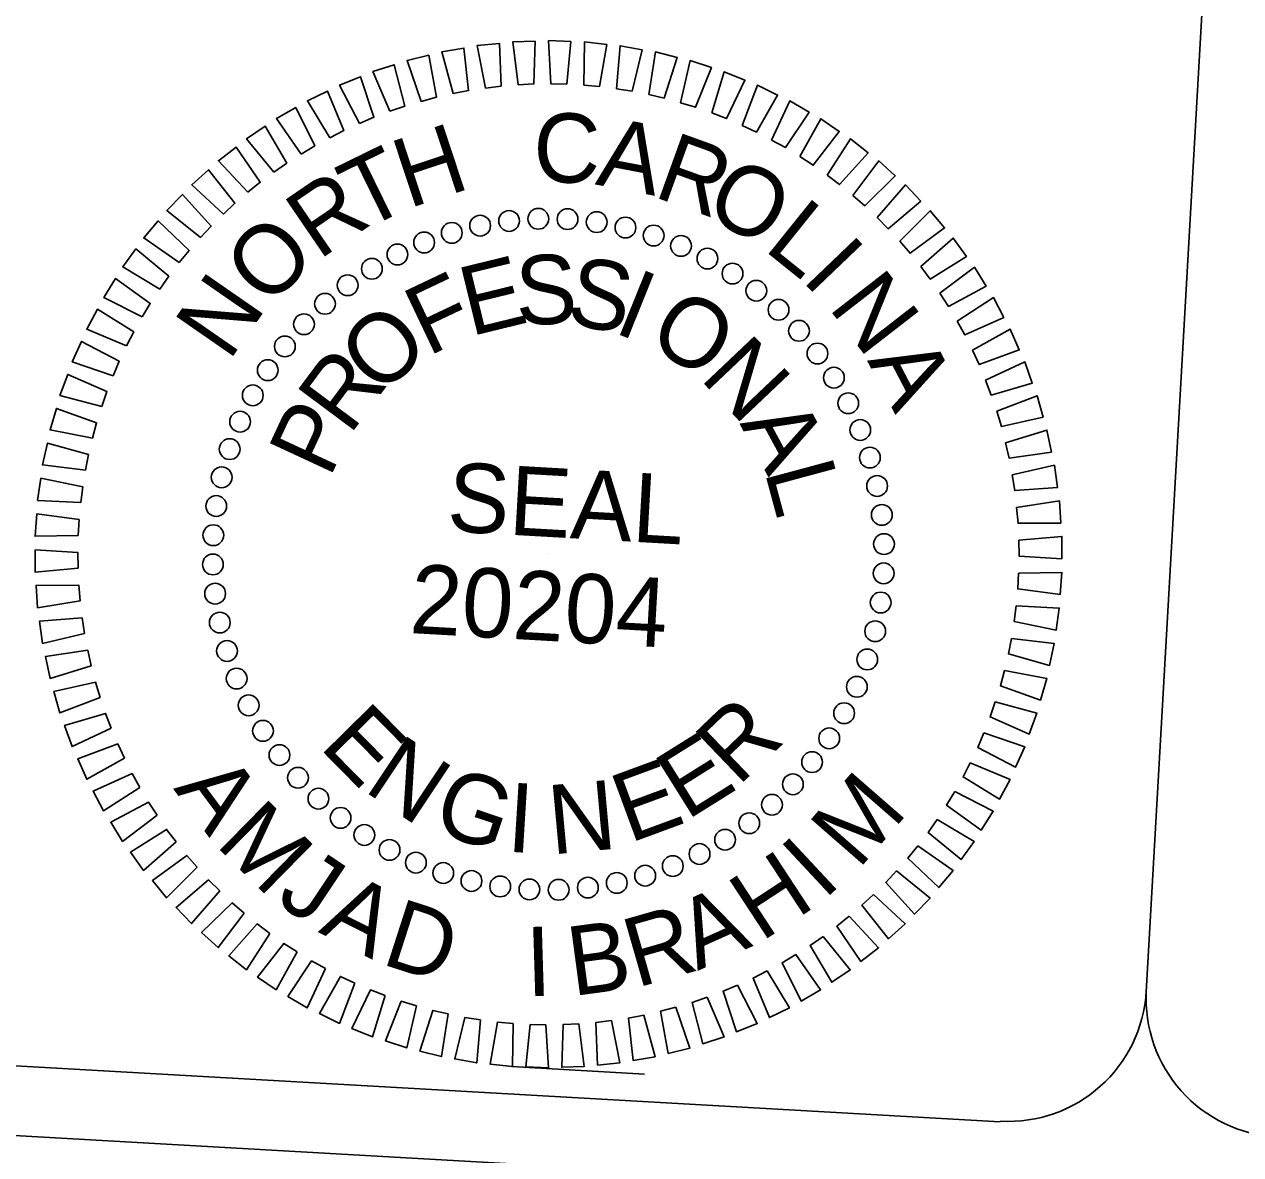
# Model space of a CAD drawing. Extents: x 2601627 to 2606907, y 616646 to 620530.
# Drawn here: x 2605867.9 to 2606131.5, y 617064.3 to 617309.3 of the extents above; entities that cross this region are included whole.
import ezdxf

# ---------------------------------------------------------------- set-up
doc = ezdxf.new("R2010")
doc.units = 0
doc.layers.add('Sheet PE Seal Cell', color=7, linetype='Continuous')
doc.layers.add('Sheet Title CELL', color=7, linetype='Continuous')

msp = doc.modelspace()

# ---------------------------------------------------------------- linework, layer by layer
at = {"layer": 'Sheet PE Seal Cell'}
msp.add_line((2605981.51, 617194.47), (2605981.51, 617194.47), dxfattribs=at)
for points in [[(2605967.85, 617295.52), (2605966.05, 617304.71), (2605970.87, 617305.19), (2605971.25, 617295.94)], [(2605974.93, 617296.23), (2605973.78, 617305.52), (2605978.62, 617305.66), (2605978.36, 617296.41)], [(2605982.05, 617296.44), (2605981.54, 617305.79), (2605986.39, 617305.59), (2605985.47, 617296.38)], [(2605989.16, 617296.15), (2605989.31, 617305.51), (2605994.13, 617304.98), (2605992.57, 617295.86)], [(2605996.23, 617295.37), (2605997.03, 617304.7), (2606001.81, 617303.83), (2605999.62, 617294.84)], [(2605953.92, 617292.63), (2605950.86, 617301.48), (2605955.57, 617302.63), (2605957.23, 617293.53)], [(2605960.83, 617294.32), (2605958.4, 617303.36), (2605963.18, 617304.18), (2605964.2, 617294.98)], [(2606003.24, 617294.1), (2606004.69, 617303.35), (2606009.39, 617302.15), (2606006.58, 617293.33)], [(2605947.14, 617290.47), (2605943.47, 617299.08), (2605948.09, 617300.56), (2605950.38, 617291.59)], [(2606010.13, 617292.34), (2606012.23, 617301.47), (2606016.83, 617299.94), (2606013.41, 617291.34)], [(2605940.53, 617287.84), (2605936.26, 617296.17), (2605940.77, 617297.97), (2605943.68, 617289.18)], [(2606016.89, 617290.11), (2606019.61, 617299.06), (2606024.1, 617297.22), (2606020.09, 617288.88)], [(2605934.11, 617284.75), (2605929.28, 617292.77), (2605933.65, 617294.87), (2605937.16, 617286.31)], [(2606023.48, 617287.4), (2606026.82, 617296.15), (2606031.17, 617294), (2606026.59, 617285.96)], [(2605927.93, 617281.22), (2605922.55, 617288.89), (2605926.76, 617291.29), (2605930.86, 617283)], [(2606029.86, 617284.25), (2606033.8, 617292.74), (2606037.99, 617290.3), (2606032.86, 617282.6)], [(2606036, 617280.66), (2606040.53, 617288.86), (2606044.53, 617286.12), (2606038.88, 617278.8)], [(2605922.01, 617277.28), (2605916.11, 617284.54), (2605920.14, 617287.23), (2605924.81, 617279.25)], [(2606041.88, 617276.65), (2606046.97, 617284.51), (2606050.78, 617281.51), (2606044.62, 617274.59)], [(2605916.38, 617272.92), (2605909.98, 617279.76), (2605913.82, 617282.73), (2605919.04, 617275.09)], [(2606047.47, 617272.24), (2606053.09, 617279.72), (2606056.68, 617276.46), (2606050.06, 617269.99)], [(2605911.06, 617268.19), (2605904.21, 617274.56), (2605907.83, 617277.79), (2605913.57, 617270.53)], [(2606052.73, 617267.45), (2606058.86, 617274.52), (2606062.21, 617271.02), (2606055.16, 617265.03)], [(2605906.09, 617263.09), (2605898.81, 617268.97), (2605902.19, 617272.45), (2605908.42, 617265.61)], [(2606057.65, 617262.3), (2606064.26, 617268.93), (2606067.36, 617265.2), (2606059.9, 617259.72)], [(2605901.49, 617257.67), (2605893.81, 617263.02), (2605896.95, 617266.72), (2605903.64, 617260.33)], [(2606062.2, 617256.83), (2606069.25, 617262.98), (2606072.08, 617259.04), (2606064.26, 617254.09)], [(2605897.27, 617251.93), (2605889.24, 617256.74), (2605892.11, 617260.65), (2605899.24, 617254.74)], [(2606066.35, 617251.05), (2606073.82, 617256.69), (2606076.37, 617252.57), (2606068.22, 617248.18)], [(2605893.47, 617245.91), (2605885.12, 617250.15), (2605887.71, 617254.25), (2605895.23, 617248.85)], [(2606070.09, 617244.99), (2606077.93, 617250.1), (2606080.19, 617245.81), (2606071.76, 617242)], [(2605890.1, 617239.65), (2605881.47, 617243.29), (2605883.77, 617247.56), (2605891.65, 617242.7)], [(2606073.4, 617238.69), (2606081.58, 617243.24), (2606083.53, 617238.8), (2606074.85, 617235.59)], [(2605887.17, 617233.16), (2605878.31, 617236.19), (2605880.31, 617240.61), (2605888.5, 617236.32)], [(2606076.26, 617232.17), (2606084.74, 617236.14), (2606086.37, 617231.58), (2606077.49, 617228.97)], [(2605884.7, 617226.48), (2605875.65, 617228.89), (2605877.33, 617233.44), (2605885.81, 617229.73)], [(2606078.66, 617225.47), (2606087.39, 617228.84), (2606088.71, 617224.17), (2606079.67, 617222.19)], [(2605882.7, 617219.65), (2605873.51, 617221.42), (2605874.87, 617226.08), (2605883.58, 617222.96)], [(2606080.59, 617218.62), (2606089.53, 617221.37), (2606090.52, 617216.62), (2606081.36, 617215.28)], [(2605881.19, 617212.7), (2605871.89, 617213.82), (2605872.92, 617218.56), (2605881.83, 617216.06)], [(2606082.03, 617211.65), (2606091.15, 617213.77), (2606091.8, 617208.96), (2606082.57, 617208.26)], [(2605880.16, 617205.66), (2605870.81, 617206.13), (2605871.51, 617210.93), (2605880.57, 617209.06)], [(2606082.98, 617204.6), (2606092.23, 617206.07), (2606092.54, 617201.24), (2606083.29, 617201.18)], [(2605879.62, 617198.56), (2605870.26, 617198.38), (2605870.63, 617203.21), (2605879.8, 617201.98)], [(2606083.44, 617197.49), (2606092.77, 617198.32), (2606092.74, 617193.47), (2606083.51, 617194.07)], [(2605879.59, 617191.44), (2605870.26, 617190.61), (2605870.29, 617195.46), (2605879.52, 617194.87)], [(2606083.4, 617190.38), (2606092.77, 617190.55), (2606092.4, 617185.72), (2606083.23, 617186.95)], [(2605880.05, 617184.34), (2605870.8, 617182.86), (2605870.49, 617187.7), (2605879.74, 617187.75)], [(2606082.87, 617183.28), (2606092.22, 617182.8), (2606091.52, 617178), (2606082.46, 617179.88)], [(2605881, 617177.28), (2605871.88, 617175.16), (2605871.23, 617179.97), (2605880.46, 617180.67)], [(2606081.84, 617176.23), (2606091.14, 617175.11), (2606090.11, 617170.37), (2606081.2, 617172.87)], [(2605882.44, 617170.31), (2605873.49, 617167.56), (2605872.51, 617172.31), (2605881.67, 617173.65)], [(2606080.33, 617169.28), (2606089.52, 617167.51), (2606088.16, 617162.85), (2606079.45, 617165.97)], [(2605884.37, 617163.46), (2605875.63, 617160.09), (2605874.32, 617164.76), (2605883.36, 617166.74)], [(2606078.33, 617162.45), (2606087.38, 617160.04), (2606085.7, 617155.49), (2606077.22, 617159.21)], [(2605886.77, 617156.76), (2605878.29, 617152.79), (2605876.65, 617157.36), (2605885.53, 617159.96)], [(2606075.86, 617155.77), (2606084.72, 617152.74), (2606082.72, 617148.32), (2606074.53, 617152.62)], [(2605889.63, 617150.24), (2605881.45, 617145.69), (2605879.5, 617150.13), (2605888.18, 617153.35)], [(2606072.93, 617149.29), (2606081.56, 617145.64), (2606079.26, 617141.37), (2606071.38, 617146.23)], [(2605892.94, 617143.94), (2605885.09, 617138.83), (2605882.84, 617143.12), (2605891.27, 617146.94)], [(2606069.56, 617143.02), (2606077.91, 617138.78), (2606075.32, 617134.68), (2606067.8, 617140.08)], [(2605896.68, 617137.89), (2605889.21, 617132.24), (2605886.66, 617136.37), (2605894.81, 617140.76)], [(2606065.75, 617137), (2606073.79, 617132.19), (2606070.92, 617128.29), (2606063.79, 617134.19)], [(2605900.83, 617132.11), (2605893.78, 617125.95), (2605890.95, 617129.89), (2605898.76, 617134.84)], [(2606061.54, 617131.27), (2606069.22, 617125.91), (2606066.08, 617122.21), (2606059.39, 617128.6)], [(2605905.38, 617126.63), (2605898.77, 617120), (2605895.67, 617123.73), (2605903.13, 617129.21)], [(2606056.94, 617125.84), (2606064.22, 617119.96), (2606060.84, 617116.49), (2606054.6, 617123.33)], [(2605910.3, 617121.49), (2605904.17, 617114.41), (2605900.81, 617117.91), (2605907.87, 617123.9)], [(2606051.97, 617120.74), (2606058.82, 617114.37), (2606055.2, 617111.14), (2606049.46, 617118.4)], [(2605915.56, 617116.69), (2605909.94, 617109.21), (2605906.35, 617112.47), (2605912.97, 617118.94)], [(2606046.65, 617116.01), (2606053.05, 617109.17), (2606049.21, 617106.21), (2606043.99, 617113.85)], [(2605921.15, 617112.28), (2605916.06, 617104.42), (2605912.25, 617107.43), (2605918.41, 617114.34)], [(2605927.03, 617108.27), (2605922.5, 617100.08), (2605918.49, 617102.81), (2605924.15, 617110.13)], [(2606041.02, 617111.66), (2606046.92, 617104.39), (2606042.89, 617101.7), (2606038.22, 617109.69)], [(2606035.1, 617107.71), (2606040.48, 617100.05), (2606036.27, 617097.64), (2606032.16, 617105.94)], [(2605933.17, 617104.68), (2605929.23, 617096.19), (2605925.04, 617098.64), (2605930.17, 617106.34)], [(2606028.92, 617104.18), (2606033.75, 617096.16), (2606029.38, 617094.06), (2606025.87, 617102.62)], [(2605939.55, 617101.53), (2605936.21, 617092.78), (2605931.86, 617094.93), (2605936.44, 617102.97)], [(2605946.14, 617098.83), (2605943.41, 617089.87), (2605938.93, 617091.71), (2605942.94, 617100.05)], [(2606022.5, 617101.09), (2606026.77, 617092.76), (2606022.26, 617090.97), (2606019.35, 617099.75)], [(2605952.9, 617096.59), (2605950.8, 617087.47), (2605946.2, 617088.99), (2605949.62, 617097.59)], [(2606009.11, 617096.3), (2606012.17, 617087.45), (2606007.46, 617086.3), (2606005.8, 617095.41)], [(2606015.89, 617098.46), (2606019.56, 617089.85), (2606014.94, 617088.38), (2606012.65, 617097.34)], [(2605959.79, 617094.83), (2605958.34, 617085.59), (2605953.64, 617086.78), (2605956.45, 617095.6)], [(2605966.8, 617093.56), (2605965.99, 617084.23), (2605961.22, 617085.1), (2605963.41, 617094.09)], [(2606002.19, 617094.61), (2606004.63, 617085.57), (2605999.85, 617084.76), (2605998.83, 617093.95)], [(2605973.87, 617092.78), (2605973.72, 617083.42), (2605968.9, 617083.95), (2605970.46, 617093.07)], [(2605980.98, 617092.5), (2605981.49, 617083.15), (2605976.64, 617083.34), (2605977.55, 617092.55)], [(2605988.1, 617092.71), (2605989.25, 617083.42), (2605984.41, 617083.27), (2605984.67, 617092.52)], [(2605995.18, 617093.41), (2605996.98, 617084.23), (2605992.15, 617083.74), (2605991.78, 617092.99)]]:
    msp.add_lwpolyline(points, close=True, dxfattribs=at)
for centre in [(2605966.71, 617265.69), (2605972.98, 617266.71), (2605979.31, 617267.18), (2605985.65, 617267.1), (2605991.97, 617266.46), (2605960.56, 617264.13), (2605998.2, 617265.28), (2606004.31, 617263.55), (2605954.57, 617262.04), (2606010.24, 617261.3), (2605948.78, 617259.44), (2606015.96, 617258.55), (2605943.24, 617256.34), (2606021.41, 617255.3), (2605938, 617252.77), (2606026.56, 617251.59), (2605933.08, 617248.75), (2606031.37, 617247.45), (2605928.53, 617244.32), (2606035.8, 617242.9), (2605924.39, 617239.52), (2606039.81, 617237.98), (2605920.68, 617234.37), (2606043.38, 617232.74), (2605917.44, 617228.91), (2606046.48, 617227.2), (2605914.68, 617223.2), (2606049.09, 617221.41), (2605912.43, 617217.26), (2606051.18, 617215.42), (2605910.7, 617211.15), (2606052.74, 617209.27), (2605909.52, 617204.92), (2606053.76, 617203), (2605908.88, 617198.6), (2606054.23, 617196.68), (2605908.8, 617192.26), (2606054.15, 617190.33), (2605909.27, 617185.93), (2606053.51, 617184.01), (2605910.29, 617179.66), (2606052.32, 617177.78), (2605911.85, 617173.51), (2606050.6, 617171.67), (2605913.94, 617167.52), (2606048.35, 617165.74), (2605916.54, 617161.73), (2606045.59, 617160.02), (2605919.64, 617156.2), (2606042.35, 617154.57), (2605923.22, 617150.95), (2606038.64, 617149.42), (2605927.23, 617146.03), (2606034.49, 617144.61), (2605931.66, 617141.49), (2606029.95, 617140.18), (2605936.47, 617137.34), (2606025.03, 617136.17), (2605941.62, 617133.63), (2606019.79, 617132.6), (2605947.07, 617130.39), (2606014.25, 617129.5), (2605952.79, 617127.63), (2606008.46, 617126.89), (2605958.72, 617125.38), (2605964.83, 617123.66), (2605996.32, 617123.24), (2606002.47, 617124.8), (2605971.06, 617122.47), (2605977.38, 617121.83), (2605983.72, 617121.75), (2605990.05, 617122.22)]:
    msp.add_circle(centre, 2.25, dxfattribs=at)
at = {"layer": 'Sheet Title CELL'}
for p, q in [((2606111.05, 617099.66), (2606138.35, 617578.89)), ((2605973.59, 617083.43), (2606002.36, 617081.8))]:
    msp.add_line(p, q, dxfattribs=at)
for points in [[(2602185.54, 617278.13), (2606618.35, 617025.66)], [(2605481.05, 617105.5), (2606079.41, 617071.42)]]:
    msp.add_lwpolyline(points, dxfattribs=at)
for centre, start, end in [((2606081.12, 617101.54), 266.7403, 356.7403), ((2606141.03, 617098.13), 176.7403, 266.7403)]:
    msp.add_arc(centre, 30, start, end, dxfattribs=at)

# ---------------------------------------------------------------- texts
at = {"layer": 'Sheet PE Seal Cell'}
for s, rotation, p in [('C', 358.7016, (2605978.09, 617275.19)), ('H', 18.3408, (2605951.16, 617269.34)), ('A', 349.1966, (2605991.47, 617274.65)), ('R', 340.1491, (2606003.95, 617272.08)), ('T', 26.13, (2605941.29, 617264.54)), ('O', 331.9404, (2606014.81, 617268.08)), ('R', 34.3387, (2605931.7, 617258.08)), ('L', 321.2152, (2606027.93, 617260.6)), ('O', 45.0639, (2605920.73, 617247.7)), ('I', 313.7501, (2606036.12, 617254.01)), ('S', 1.9635, (2605974.56, 617244.13)), ('E', 13.7257, (2605964.58, 617241.67)), ('S', 350.0045, (2605985, 617244.5)), ('N', 55.2743, (2605912.26, 617236.08)), ('F', 25.4037, (2605955.38, 617237.27)), ('I', 338.0456, (2605995.29, 617242.69)), ('N', 307.8101, (2606041.99, 617248.04)), ('O', 329.2901, (2606002.47, 617240.03)), ('O', 41.2124, (2605944.7, 617228.53)), ('N', 313.4814, (2606014.09, 617232.6)), ('R', 53.3119, (2605938.38, 617220.05)), ('A', 297.5997, (2606050.53, 617236.47)), ('P', 65.0741, (2605934.07, 617210.73)), ('A', 298.4313, (2606022.87, 617222.83)), ('L', 285.0954, (2606028.3, 617212.52)), ('SEAL', 356.7398, (2605959.34, 617199.49)), ('20204', 356.7398, (2605951.25, 617177.41)), ('R', 43.7827, (2606022.61, 617144)), ('E', 314.5904, (2605931.63, 617152.66)), ('N', 326.3526, (2605941.2, 617143.37)), ('E', 32.0205, (2606011.46, 617136.68)), ('E', 20.2582, (2605999.05, 617131.79)), ('A', 306.4867, (2605900.14, 617143.67)), ('G', 341.4027, (2605955.85, 617134.65)), ('M', 48.9292, (2606048.65, 617125.95)), ('I', 356.4527, (2605972.26, 617130.04)), ('N', 5.2082, (2605982.18, 617129.38)), ('M', 315.5342, (2605909.14, 617131.51)), ('I', 42.9893, (2606041.19, 617119.37)), ('J', 326.2403, (2605922.1, 617119.16)), ('H', 33.2364, (2606027.61, 617110.35)), ('A', 333.0782, (2605931.49, 617112.62)), ('A', 24.1889, (2606013.81, 617104.14)), ('D', 342.1257, (2605944.98, 617105.77)), ('R', 15.9803, (2606000.58, 617100.46)), ('B', 7.6382, (2605986.74, 617098.69)), ('I', 1.6982, (2605976.8, 617098.66))]:
    msp.add_text(s, height=15, rotation=rotation, dxfattribs=at).set_placement(p)

doc.saveas('drawing.dxf')
